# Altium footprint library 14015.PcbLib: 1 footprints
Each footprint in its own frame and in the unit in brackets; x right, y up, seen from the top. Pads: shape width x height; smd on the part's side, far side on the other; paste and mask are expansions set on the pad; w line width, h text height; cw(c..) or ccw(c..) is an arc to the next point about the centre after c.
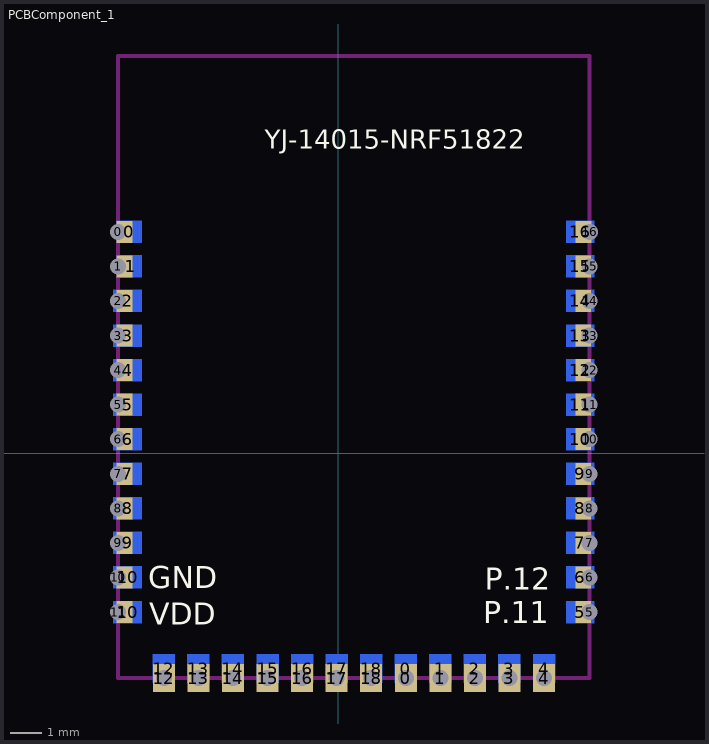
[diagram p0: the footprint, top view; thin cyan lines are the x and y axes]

## PCBComponent_1 [mm]
pads (72):
  rect 0.5x0.7 hole 0.508 copper offset 0.2,0: 0(-7.003,7.046) 1(-7.003,5.946) 2(-7.003,4.846) 3(-7.003,3.746) 4(-7.003,2.646) 5(-7.003,1.546) 6(-7.003,0.446) 7(-7.003,-0.654) 8(-7.003,-1.754) 9(-7.003,-2.854) 10(-7.003,-3.954) 11(-7.003,-5.054)
  rect 0.8x0.7 smd far side: 0(-6.653,7.046)
  rect 0.7x0.9 smd far side: 0(2.147,-6.854) 1(3.247,-6.854) 2(4.347,-6.854) 3(5.447,-6.854) 4(6.547,-6.854) 12(-5.553,-6.854) 13(-4.453,-6.854) 14(-3.353,-6.854) 15(-2.253,-6.854) 16(-1.153,-6.854) 17(-0.053,-6.854) 18(1.047,-6.854)
  rect 0.7x0.9 hole 0.508: 0(2.147,-7.154) 1(3.247,-7.154) 2(4.347,-7.154) 3(5.447,-7.154) 4(6.547,-7.154) 12(-5.553,-7.154) 13(-4.453,-7.154) 14(-3.353,-7.154) 15(-2.253,-7.154) 16(-1.153,-7.154) 17(-0.053,-7.154) 18(1.047,-7.154)
  rect 0.7x0.7 smd far side: 1(-6.608,5.946)
  rect 0.9x0.7 smd far side: 2(-6.708,4.846) 3(-6.708,3.746) 4(-6.708,2.646) 5(-6.708,1.546) 5(7.697,-5.054) 6(-6.708,0.446) 6(7.697,-3.954) 7(-6.708,-0.654) 7(7.697,-2.854) 8(-6.708,-1.754) 8(7.697,-1.754) 9(-6.708,-2.854) 9(7.697,-0.654) 10(-6.708,-5.054) 10(-6.708,-3.954) 10(7.697,0.446) 11(7.697,1.546) 12(7.697,2.646) 13(7.697,3.746) 14(7.697,4.846) 15(7.697,5.946) 16(7.697,7.046)
  rect 0.5x0.7 hole 0.508 copper offset -0.2,0: 5(7.997,-5.054) 6(7.997,-3.954) 7(7.997,-2.854) 8(7.997,-1.754) 9(7.997,-0.654) 10(7.997,0.446) 11(7.997,1.546) 12(7.997,2.646) 13(7.997,3.746) 14(7.997,4.846) 15(7.997,5.946) 16(8.002,7.046)
Top Overlay:
  text "YJ-14015-NRF51822" at -2.343,9.686 h0.6
  text "P.11" at 4.617,-5.404 h0.7
  text "P.12" at 4.657,-4.344 h0.7
  text "VDD" at -6.023,-5.454 h0.7
  text "GND" at -6.043,-4.304 h0.7
Bottom Overlay:
  text "P0.15" at 3.897,-1.044 h0.7
  text "GND" at -6.043,6.656 h0.7
  text "P.21" at -6.023,5.586 h0.7
  text "P.22" at -6.003,4.496 h0.7
  text "P.23" at -5.993,3.446 h0.7
  text "P.24" at -6.003,2.346 h0.7
  text "P.25" at -5.983,1.196 h0.7
  text "P.28" at -5.993,-1.944 h0.7
  text "P.29" at -5.973,-3.244 h0.7
  text "P.30" at -5.783,-3.744 h0.7
  text "P.00" at -4.663,-3.744 h0.7
  text "P.01" at -3.543,-3.744 h0.7
  text "P.02" at -2.533,-3.764 h0.7
  text "P.03" at -1.433,-3.764 h0.7
  text "P.04" at -0.313,-3.784 h0.7
  text "P.05" at 0.677,-3.754 h0.7
  text "P.06" at 1.807,-3.654 h0.7
  text "P.07" at 2.847,-3.654 h0.7
  text "P.08" at 4.157,-3.654 h0.7
  text "P.09" at 5.157,-3.654 h0.7
  text "P.10" at 6.237,-3.684 h0.7
  text "P0.13" at 3.807,-3.224 h0.7
  text "P0.14" at 3.897,-2.094 h0.7
  text "P0.16" at 3.897,0.146 h0.7
  text "SWDIO" at 3.877,1.266 h0.7
  text "SCLK" at 4.427,2.446 h0.7
  text "P0.17" at 3.927,3.326 h0.7
  text "P0.18" at 3.947,4.426 h0.7
  text "P0.19" at 3.957,5.636 h0.7
  text "P0.20" at 3.847,6.706 h0.7
Keep-Out Layer:
  lines w0.127: -7.003,-7.154 7.997,-7.154 7.997,12.646 -7.003,12.646 -7.003,-7.154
